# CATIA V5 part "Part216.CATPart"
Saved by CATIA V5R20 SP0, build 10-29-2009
Part number: FA 168700-3
Revision: ANY
Definition: UNKNOWN
Nomenclature: FA 168700-3
Source: Unknown
Bounding box of the stored display mesh (mm): x -3 to 3, y 0 to 4.95, z -3.464 to 3.464
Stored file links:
  C:\Users\Utente\Desktop\IO LAVORO\3D X SITO CF\CUMSA\3D files FA\FA 200710-20\Part216.CATPart

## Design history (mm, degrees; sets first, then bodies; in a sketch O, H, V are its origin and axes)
Body1 "Cortar-Extruir3" (main body)
  Solid1: solid without history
